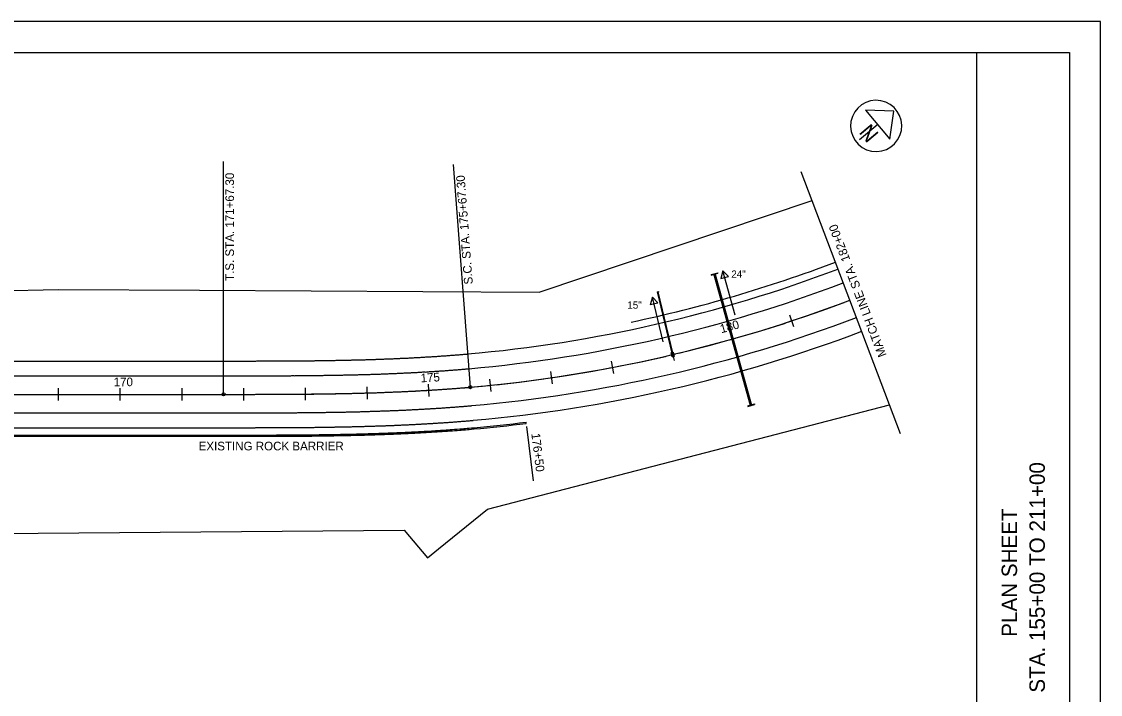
# Model space of a CAD drawing. Extents: x 0 to 3400, y 0 to 2200.
# Drawn here: x 1652 to 3400, y 1110 to 2200 of the extents above; entities that cross this region are included whole.
import ezdxf

# ---------------------------------------------------------------- set-up
doc = ezdxf.new("R2010")
doc.units = 0
for name, color, linetype in [('Default', 7, 'Continuous'), ('DR_X_Culvert', 7, 'Continuous'), ('DR_X_Text', 7, 'Continuous'), ('GE_P_CL_100', 7, 'Continuous'), ('PV_P_EOP', 7, 'Continuous'), ('PV_X_EOP', 7, 'Continuous'), ('RD_X_GR_Lt', 7, 'Continuous'), ('RW_X_Esmt_LA', 7, 'Continuous'), ('SC_Scratch10', 7, 'Continuous'), ('SH_Border', 7, 'Continuous'), ('SH_Cut_Line', 7, 'Continuous'), ('SH_Data', 7, 'Continuous')]:
    doc.layers.add(name, color=color, linetype=linetype)

msp = doc.modelspace()

# ---------------------------------------------------------------- linework, layer by layer
at = {"layer": 'Default'}
for p, q in [((2995.2, 1745.7), (2994.1, 1748.5)), ((2903.1, 1705.5), (2896.7, 1724.4)), ((2648.5, 1702.5), (2648.5, 1702.5)), ((2807, 1676.1), (2801.6, 1695.3)), ((2804.3, 1685.7), (2804.3, 1685.7)), ((2709.9, 1650.8), (2705.2, 1670.2)), ((2707.5, 1660.5), (2707.5, 1660.5)), ((2611.6, 1629.8), (2607.9, 1649.5)), ((2512.6, 1613.1), (2509.7, 1632.9)), ((2212.6, 1588.2), (2212, 1608.2)), ((2312.8, 1592.6), (2311.6, 1612.6)), ((2412.9, 1600.6), (2411, 1620.5)), ((312.1, 1595.9), (1979.7, 1595.9)), ((1712.3, 1585.9), (1712.3, 1605.9)), ((1812.3, 1585.9), (1812.3, 1605.9)), ((1912.3, 1585.9), (1912.3, 1605.9)), ((2012.3, 1585.9), (2012.3, 1605.9)), ((2112.4, 1586.3), (2112.2, 1606.3)), ((2312.2, 1602.6), (2312.2, 1602.6))]:
    msp.add_line(p, q, dxfattribs=at)
for points in [[(2989.5, 1746.7), (2994.1, 1748.5)], [(2909.4, 1718.2), (2925.7, 1723.7), (2963.4, 1737.1), (2984.8, 1745)], [(2895.2, 1713.4), (2899.9, 1715)], [(2899.9, 1715), (2904.7, 1716.6)], [(2813.9, 1688.4), (2849.7, 1698.9), (2888, 1710.9), (2890.4, 1711.8)], [(2717.3, 1662.8), (2734, 1666.9), (2772.9, 1677), (2794.7, 1683)], [(2799.5, 1684.4), (2804.3, 1685.7)], [(2804.3, 1685.7), (2809.1, 1687.1)], [(2702.7, 1659.3), (2707.5, 1660.5)], [(2707.5, 1660.5), (2712.4, 1661.6)], [(2619.6, 1641.5), (2656.2, 1648.8), (2695.3, 1657.5), (2697.8, 1658.1)], [(2521, 1624.5), (2538.3, 1627), (2577.7, 1633.6), (2599.9, 1637.8)], [(2604.8, 1638.7), (2609.7, 1639.6)], [(2609.7, 1639.6), (2614.7, 1640.6)], [(2322.2, 1603.2), (2324.2, 1603.4), (2327.2, 1603.6), (2330.3, 1603.8), (2333.4, 1604), (2336.4, 1604.2), (2339.5, 1604.4), (2342.6, 1604.6), (2345.6, 1604.8), (2348.7, 1605.1), (2351.8, 1605.3), (2354.8, 1605.5), (2357.9, 1605.8), (2361, 1606), (2364.1, 1606.3), (2367.1, 1606.5), (2370.2, 1606.8), (2373.3, 1607), (2376.3, 1607.3), (2379.4, 1607.6), (2379.4, 1607.6), (2402, 1609.7)], [(2406.9, 1610.1), (2411.9, 1610.6)], [(2411.9, 1610.6), (2416.9, 1611.1)], [(2421.9, 1611.6), (2458.9, 1615.9), (2498.5, 1621.2), (2501.2, 1621.6)], [(2506.2, 1622.3), (2511.1, 1623)], [(2511.1, 1623), (2516.1, 1623.8)], [(1622.3, 1595.9), (1702.3, 1595.9)], [(1707.3, 1595.9), (1717.3, 1595.9)], [(1722.3, 1595.9), (1802.3, 1595.9)], [(1807.3, 1595.9), (1817.3, 1595.9)], [(1822.3, 1595.9), (1902.3, 1595.9)], [(1907.3, 1595.9), (1917.3, 1595.9)], [(1922.3, 1595.9), (1979.7, 1595.9), (1979.7, 1595.9), (1982.8, 1595.9), (1985.8, 1595.9), (1988.9, 1595.9), (1992, 1595.9), (1995.1, 1595.9), (1998.1, 1595.9), (2001.2, 1595.9), (2002.3, 1595.9)], [(2007.3, 1595.9), (2007.4, 1595.9), (2010.5, 1595.9), (2013.5, 1595.9), (2016.6, 1595.9), (2017.3, 1595.9)], [(2022.3, 1595.9), (2022.8, 1595.9), (2025.8, 1595.9), (2028.9, 1595.9), (2032, 1596), (2035.1, 1596), (2038.1, 1596), (2041.2, 1596), (2044.3, 1596), (2047.4, 1596), (2050.4, 1596), (2053.5, 1596), (2056.6, 1596), (2059.7, 1596), (2062.8, 1596), (2065.8, 1596), (2068.9, 1596.1), (2072, 1596.1), (2075.1, 1596.1), (2078.1, 1596.1), (2081.2, 1596.1), (2084.3, 1596.1), (2087.4, 1596.2), (2090.4, 1596.2), (2093.5, 1596.2), (2096.6, 1596.2), (2099.7, 1596.2), (2102.3, 1596.3)], [(2107.3, 1596.3), (2108.9, 1596.3), (2112, 1596.3), (2115.1, 1596.4), (2117.3, 1596.4)], [(2122.3, 1596.5), (2124.3, 1596.5), (2127.4, 1596.5), (2130.4, 1596.5), (2133.5, 1596.6), (2136.6, 1596.6), (2139.7, 1596.7), (2142.8, 1596.7), (2145.8, 1596.8), (2148.9, 1596.8), (2152, 1596.9), (2155.1, 1596.9), (2158.1, 1597), (2161.2, 1597), (2164.3, 1597.1), (2167.4, 1597.1), (2170.4, 1597.2), (2173.5, 1597.2), (2176.6, 1597.3), (2179.7, 1597.4), (2182.7, 1597.4), (2185.8, 1597.5), (2188.9, 1597.6), (2192, 1597.7), (2195, 1597.7), (2198.1, 1597.8), (2201.2, 1597.9), (2202.3, 1597.9)], [(2207.3, 1598.1), (2207.4, 1598.1), (2210.4, 1598.2), (2213.5, 1598.2), (2216.6, 1598.3), (2217.3, 1598.4)], [(2222.3, 1598.5), (2222.7, 1598.5), (2225.8, 1598.6), (2228.9, 1598.7), (2232, 1598.8), (2235, 1599), (2238.1, 1599.1), (2241.2, 1599.2), (2244.3, 1599.3), (2247.3, 1599.4), (2250.4, 1599.5), (2253.5, 1599.7), (2256.6, 1599.8), (2259.6, 1599.9), (2262.7, 1600), (2265.8, 1600.2), (2268.8, 1600.3), (2271.9, 1600.5), (2275, 1600.6), (2278.1, 1600.8), (2281.1, 1600.9), (2284.2, 1601.1), (2287.3, 1601.2), (2290.4, 1601.4), (2293.4, 1601.5), (2296.5, 1601.7), (2299.6, 1601.9), (2302.3, 1602)], [(2307.2, 1602.3), (2308.8, 1602.4), (2311.9, 1602.6), (2312.1, 1602.6), (2312.2, 1602.6)], [(2312.2, 1602.6), (2315.1, 1602.8), (2317.2, 1602.9)]]:
    msp.add_lwpolyline(points, dxfattribs=at)
msp.add_arc((2179.6, 3890.7), 2291.8, 274.9999, 290.8177, dxfattribs=at)
for points in [[(1979.7, 1595.9), (1985.8, 1595.9), (1992, 1595.9), (1998.1, 1595.9), (2004.3, 1595.9), (2010.5, 1595.9), (2016.6, 1595.9), (2022.8, 1595.9), (2028.9, 1595.9), (2035.1, 1596), (2041.2, 1596), (2047.4, 1596), (2053.5, 1596), (2059.7, 1596), (2065.8, 1596), (2072, 1596.1), (2078.1, 1596.1), (2084.3, 1596.1), (2090.4, 1596.2), (2096.6, 1596.2), (2102.8, 1596.3), (2108.9, 1596.3), (2115.1, 1596.4), (2121.2, 1596.4), (2127.4, 1596.5), (2133.5, 1596.6), (2139.7, 1596.7), (2145.8, 1596.8), (2152, 1596.9), (2158.1, 1597), (2164.3, 1597.1), (2170.4, 1597.2), (2176.6, 1597.3), (2182.7, 1597.4), (2188.9, 1597.6), (2195, 1597.7), (2201.2, 1597.9), (2207.4, 1598.1), (2213.5, 1598.2), (2219.7, 1598.4), (2225.8, 1598.6), (2232, 1598.8), (2238.1, 1599.1), (2244.3, 1599.3), (2250.4, 1599.5), (2256.6, 1599.8), (2262.7, 1600), (2268.8, 1600.3), (2275, 1600.6), (2281.1, 1600.9), (2287.3, 1601.2), (2293.4, 1601.5), (2299.6, 1601.9), (2305.7, 1602.2), (2311.9, 1602.6), (2312.2, 1602.6)], [(2312.2, 1602.6), (2318, 1603), (2324.2, 1603.4), (2330.3, 1603.8), (2336.4, 1604.2), (2342.6, 1604.6), (2348.7, 1605.1), (2354.8, 1605.5), (2361, 1606), (2367.1, 1606.5), (2373.3, 1607), (2379.4, 1607.6)]]:
    msp.add_spline(points, degree=3, dxfattribs=at)
at = {"layer": 'DR_X_Culvert'}
for p, q in [((2769.4, 1790.2), (2780, 1793.1)), ((2769.4, 1790.2), (2769.7, 1789.2)), ((2769.7, 1789.2), (2780.3, 1792.2)), ((2833.4, 1577.6), (2773.7, 1791.4)), ((2835.4, 1578.1), (2775.7, 1791.9)), ((2780, 1793.1), (2780.3, 1792.2)), ((2681.9, 1762), (2683.9, 1762.4)), ((2681.9, 1762), (2682.1, 1761)), ((2682.1, 1761), (2684.2, 1761.5)), ((2706.3, 1662.9), (2682.3, 1762.1)), ((2707.5, 1663.2), (2683.5, 1762.3)), ((2683.9, 1762.4), (2684.2, 1761.5)), ((2704.8, 1663.2), (2708.7, 1664.2)), ((2706.4, 1656.8), (2704.8, 1663.2)), ((2705.6, 1662.7), (2708.2, 1663.4)), ((2706.9, 1657.6), (2705.6, 1662.7)), ((2709.4, 1658.2), (2708.2, 1663.4)), ((2710.3, 1657.7), (2708.7, 1664.2)), ((2706.4, 1656.8), (2710.3, 1657.7)), ((2706.9, 1657.6), (2709.4, 1658.2)), ((2828.8, 1577.3), (2839.4, 1580.3)), ((2828.8, 1577.3), (2829.1, 1576.4)), ((2829.1, 1576.4), (2839.7, 1579.3)), ((2839.4, 1580.3), (2839.7, 1579.3))]:
    msp.add_line(p, q, dxfattribs=at)
at = {"layer": 'DR_X_Text'}
for p, q in [((2788.4, 1796), (2785.2, 1783.7)), ((2785.2, 1783.8), (2797.4, 1787.1)), ((2797.4, 1787.1), (2788.4, 1796)), ((2808.3, 1724.4), (2788.4, 1796)), ((2674.4, 1753.4), (2670.8, 1741.2)), ((2683.2, 1744.2), (2674.4, 1753.4)), ((2691.9, 1681.2), (2674.4, 1753.4)), ((2670.9, 1741.4), (2683.2, 1744.2))]:
    msp.add_line(p, q, dxfattribs=at)
at = {"layer": 'PV_P_EOP'}
for p, q in [((312.1, 1649.9), (1979.7, 1649.9)), ((312.1, 1625.9), (1979.7, 1625.9)), ((312.1, 1565.9), (1979.7, 1565.9)), ((312.1, 1541.9), (1979.7, 1541.9))]:
    msp.add_line(p, q, dxfattribs=at)
for radius in [2237.8, 2261.8, 2321.8, 2345.8]:
    msp.add_arc((2179.6, 3890.7), radius, 274.9999, 290.8177, dxfattribs=at)
for points in [[(2309, 1656.5), (2314.6, 1656.9), (2320.7, 1657.2), (2326.7, 1657.6), (2332.7, 1658.1), (2338.7, 1658.5), (2344.7, 1658.9), (2350.7, 1659.4), (2356.7, 1659.8), (2362.7, 1660.3), (2368.7, 1660.8), (2374.7, 1661.3)], [(1979.7, 1649.9), (1985.8, 1649.9), (1992, 1649.9), (1998.1, 1649.9), (2004.3, 1649.9), (2010.4, 1649.9), (2016.6, 1649.9), (2022.7, 1649.9), (2028.8, 1649.9), (2035, 1650), (2041.1, 1650), (2047.2, 1650), (2053.4, 1650), (2059.5, 1650), (2065.6, 1650), (2071.7, 1650.1), (2077.9, 1650.1), (2084, 1650.1), (2090.1, 1650.2), (2096.2, 1650.2), (2102.3, 1650.3), (2108.4, 1650.3), (2114.5, 1650.4), (2120.6, 1650.4), (2126.7, 1650.5), (2132.8, 1650.6), (2138.9, 1650.7), (2145, 1650.8), (2151.1, 1650.8), (2157.2, 1650.9), (2163.3, 1651.1), (2169.4, 1651.2), (2175.5, 1651.3), (2181.5, 1651.4), (2187.6, 1651.6), (2193.7, 1651.7), (2199.8, 1651.9), (2205.8, 1652), (2211.9, 1652.2), (2218, 1652.4), (2224, 1652.6), (2230.1, 1652.8), (2236.1, 1653), (2242.2, 1653.3), (2248.2, 1653.5), (2254.3, 1653.7), (2260.3, 1654), (2266.4, 1654.3), (2272.4, 1654.5), (2278.5, 1654.8), (2284.5, 1655.1), (2290.5, 1655.5), (2296.6, 1655.8), (2302.6, 1656.1), (2308.6, 1656.5), (2309, 1656.5)], [(1979.7, 1625.9), (1985.8, 1625.9), (1992, 1625.9), (1998.1, 1625.9), (2004.3, 1625.9), (2010.4, 1625.9), (2016.6, 1625.9), (2022.7, 1625.9), (2028.9, 1625.9), (2035, 1626), (2041.2, 1626), (2047.3, 1626), (2053.4, 1626), (2059.6, 1626), (2065.7, 1626), (2071.8, 1626.1), (2078, 1626.1), (2084.1, 1626.1), (2090.2, 1626.2), (2096.4, 1626.2), (2102.5, 1626.3), (2108.6, 1626.3), (2114.8, 1626.4), (2120.9, 1626.4), (2127, 1626.5), (2133.1, 1626.6), (2139.3, 1626.7), (2145.4, 1626.8), (2151.5, 1626.8), (2157.6, 1627), (2163.7, 1627.1), (2169.8, 1627.2), (2176, 1627.3), (2182.1, 1627.4), (2188.2, 1627.6), (2194.3, 1627.7), (2200.4, 1627.9), (2206.5, 1628.1), (2212.6, 1628.2), (2218.7, 1628.4), (2224.8, 1628.6), (2230.9, 1628.8), (2237, 1629), (2243.1, 1629.3), (2249.2, 1629.5), (2255.3, 1629.8), (2261.4, 1630), (2267.5, 1630.3), (2273.6, 1630.6), (2279.7, 1630.9), (2285.7, 1631.2), (2291.8, 1631.5), (2297.9, 1631.8), (2304, 1632.2), (2310.1, 1632.5), (2310.4, 1632.6)], [(2310.4, 1632.6), (2316.1, 1632.9), (2322.2, 1633.3), (2328.3, 1633.7), (2334.4, 1634.1), (2340.4, 1634.5), (2346.5, 1635), (2352.5, 1635.4), (2358.6, 1635.9), (2364.7, 1636.4), (2370.7, 1636.9), (2376.8, 1637.4)], [(2314.1, 1572.7), (2319.9, 1573), (2326.1, 1573.4), (2332.3, 1573.8), (2338.5, 1574.3), (2344.7, 1574.7), (2350.9, 1575.2), (2357.2, 1575.6), (2363.4, 1576.1), (2369.6, 1576.6), (2375.8, 1577.1), (2382, 1577.7)], [(1979.7, 1565.9), (1985.8, 1565.9), (1992, 1565.9), (1998.1, 1565.9), (2004.3, 1565.9), (2010.5, 1565.9), (2016.6, 1565.9), (2022.8, 1565.9), (2029, 1565.9), (2035.1, 1566), (2041.3, 1566), (2047.4, 1566), (2053.6, 1566), (2059.8, 1566), (2066, 1566), (2072.1, 1566.1), (2078.3, 1566.1), (2084.5, 1566.1), (2090.6, 1566.2), (2096.8, 1566.2), (2103, 1566.3), (2109.2, 1566.3), (2115.4, 1566.4), (2121.5, 1566.4), (2127.7, 1566.5), (2133.9, 1566.6), (2140.1, 1566.7), (2146.3, 1566.8), (2152.5, 1566.9), (2158.7, 1567), (2164.8, 1567.1), (2171, 1567.2), (2177.2, 1567.3), (2183.4, 1567.5), (2189.6, 1567.6), (2195.8, 1567.7), (2202, 1567.9), (2208.2, 1568.1), (2214.4, 1568.3), (2220.6, 1568.5), (2226.8, 1568.7), (2233, 1568.9), (2239.2, 1569.1), (2245.4, 1569.3), (2251.6, 1569.6), (2257.8, 1569.8), (2264, 1570.1), (2270.2, 1570.4), (2276.4, 1570.6), (2282.6, 1570.9), (2288.8, 1571.3), (2295, 1571.6), (2301.3, 1571.9), (2307.5, 1572.3), (2313.7, 1572.6), (2314.1, 1572.7)], [(1979.7, 1541.9), (1985.8, 1541.9), (1992, 1541.9), (1998.2, 1541.9), (2004.3, 1541.9), (2010.5, 1541.9), (2016.6, 1541.9), (2022.8, 1541.9), (2029, 1541.9), (2035.2, 1542), (2041.3, 1542), (2047.5, 1542), (2053.7, 1542), (2059.9, 1542), (2066, 1542), (2072.2, 1542.1), (2078.4, 1542.1), (2084.6, 1542.1), (2090.8, 1542.2), (2097, 1542.2), (2103.2, 1542.3), (2109.4, 1542.3), (2115.6, 1542.4), (2121.8, 1542.4), (2128, 1542.5), (2134.2, 1542.6), (2140.4, 1542.7), (2146.6, 1542.8), (2152.9, 1542.9), (2159.1, 1543), (2165.3, 1543.1), (2171.5, 1543.2), (2177.7, 1543.3), (2184, 1543.5), (2190.2, 1543.6), (2196.4, 1543.8), (2202.6, 1543.9), (2208.9, 1544.1), (2215.1, 1544.3), (2221.4, 1544.5), (2227.6, 1544.7), (2233.8, 1544.9), (2240.1, 1545.1), (2246.3, 1545.3), (2252.6, 1545.6), (2258.8, 1545.8), (2265.1, 1546.1), (2271.3, 1546.4), (2277.6, 1546.7), (2283.8, 1547), (2290.1, 1547.3), (2296.3, 1547.6), (2302.6, 1548), (2308.9, 1548.3), (2315.1, 1548.7), (2315.5, 1548.7)], [(2315.5, 1548.7), (2321.4, 1549.1), (2327.7, 1549.5), (2333.9, 1549.9), (2340.2, 1550.3), (2346.5, 1550.8), (2352.7, 1551.2), (2359, 1551.7), (2365.3, 1552.2), (2371.5, 1552.7), (2377.8, 1553.2), (2384.1, 1553.8)]]:
    msp.add_spline(points, degree=3, dxfattribs=at)
at = {"layer": 'PV_X_EOP'}
for p, q in [((2470, 1548.8), (2469.7, 1550.7)), ((1612.3, 1529.9), (1979.7, 1529.9)), ((1612.3, 1527.9), (1979.7, 1527.9))]:
    msp.add_line(p, q, dxfattribs=at)
for radius in [2357.8, 2359.8]:
    msp.add_arc((2179.6, 3890.7), radius, 274.9999, 277.0669, dxfattribs=at)
for points in [[(2316.3, 1536.7), (2322, 1537.1), (2327.7, 1537.4), (2339.2, 1538.2), (2345, 1538.6), (2362.2, 1539.9), (2373.7, 1540.8), (2385.1, 1541.8)], [(2316.4, 1534.7), (2322.1, 1535.1), (2327.9, 1535.5), (2339.4, 1536.2), (2345.1, 1536.6), (2362.3, 1537.9), (2373.8, 1538.8), (2385.3, 1539.8)], [(1979.7, 1529.9), (1986.7, 1529.9), (1993.7, 1529.9), (2007.7, 1529.9), (2014.7, 1529.9), (2028.7, 1529.9), (2035.7, 1530), (2049.7, 1530), (2060.2, 1530), (2070.7, 1530.1), (2077.7, 1530.1), (2081.2, 1530.1), (2088.2, 1530.2), (2091.8, 1530.2), (2098.8, 1530.2), (2102.3, 1530.3), (2112.8, 1530.3), (2119.8, 1530.4), (2130.3, 1530.5), (2133.8, 1530.6), (2140.8, 1530.7), (2144.3, 1530.7), (2154.8, 1530.9), (2161.9, 1531), (2175.9, 1531.3), (2182.9, 1531.4), (2193.4, 1531.7), (2196.9, 1531.8), (2204, 1531.9), (2211, 1532.1), (2218, 1532.4), (2225, 1532.6), (2228.5, 1532.7), (2233.8, 1532.9), (2235.5, 1532.9), (2239.1, 1533.1), (2240.8, 1533.1), (2246.1, 1533.3), (2253.1, 1533.6), (2260.1, 1533.9), (2267.1, 1534.2), (2270.6, 1534.3), (2281.2, 1534.8), (2288.2, 1535.2), (2302.2, 1535.9), (2309.2, 1536.3), (2316.2, 1536.7)], [(1979.7, 1527.9), (1986.7, 1527.9), (1993.7, 1527.9), (2007.7, 1527.9), (2014.7, 1527.9), (2028.7, 1527.9), (2035.7, 1528), (2049.7, 1528), (2056.7, 1528), (2067.2, 1528), (2070.7, 1528.1), (2077.7, 1528.1), (2081.2, 1528.1), (2088.3, 1528.2), (2091.8, 1528.2), (2098.8, 1528.2), (2102.3, 1528.3), (2112.8, 1528.3), (2119.8, 1528.4), (2130.3, 1528.5), (2133.8, 1528.6), (2140.9, 1528.7), (2144.4, 1528.7), (2154.9, 1528.9), (2161.9, 1529), (2175.9, 1529.3), (2183, 1529.4), (2193.5, 1529.7), (2197, 1529.8), (2204, 1529.9), (2207.5, 1530), (2214.5, 1530.2), (2218.1, 1530.4), (2225.1, 1530.6), (2228.6, 1530.7), (2233.9, 1530.9), (2235.6, 1530.9), (2239.1, 1531.1), (2240.9, 1531.1), (2246.1, 1531.3), (2249.6, 1531.5), (2256.7, 1531.7), (2260.2, 1531.9), (2267.2, 1532.2), (2270.7, 1532.3), (2281.3, 1532.8), (2288.3, 1533.2), (2302.3, 1533.9), (2309.3, 1534.3), (2316.4, 1534.7)]]:
    msp.add_open_spline(points, degree=3, dxfattribs=at)
at = {"layer": 'RD_X_GR_Lt'}
msp.add_arc((2179.6, 3890.7), 2225.8, 281.9285, 290.8177, dxfattribs=at)
at = {"layer": 'RW_X_Esmt_LA'}
for p, q in [((2490.9, 1761.5), (2932.8, 1909.9)), ((812.4, 1745.9), (1712.4, 1765.9)), ((1712.4, 1765.9), (1940.4, 1764.6)), ((1940.4, 1764.6), (2302.5, 1762.5)), ((2302.5, 1762.5), (2490.9, 1761.5)), ((2406.9, 1409.9), (3058.6, 1578.9)), ((2327.9, 1345.7), (2406.9, 1409.9)), ((1012.3, 1365.9), (2271.9, 1375.7)), ((2271.9, 1375.7), (2309.9, 1331.1)), ((2309.9, 1331.1), (2327.8, 1345.6))]:
    msp.add_line(p, q, dxfattribs=at)
at = {"layer": 'SC_Scratch10'}
for p, q in [((2639.7, 1712.9), (2639.7, 1712.9)), ((2899.9, 1715), (2899.9, 1715)), ((2804.3, 1685.7), (2804.3, 1685.7)), ((2707.5, 1660.5), (2707.5, 1660.5)), ((2609.7, 1639.6), (2609.7, 1639.6)), ((2411.9, 1610.6), (2411.9, 1610.6)), ((2511.1, 1623), (2511.1, 1623)), ((1712.3, 1595.9), (1712.3, 1595.9)), ((1812.3, 1595.9), (1812.3, 1595.9)), ((1912.3, 1595.9), (1912.3, 1595.9)), ((2012.3, 1595.9), (2012.3, 1595.9)), ((2112.3, 1596.3), (2112.3, 1596.3)), ((2212.3, 1598.2), (2212.3, 1598.2)), ((2312.2, 1602.6), (2312.2, 1602.6))]:
    msp.add_line(p, q, dxfattribs=at)
at = {"layer": 'SH_Border'}
msp.add_line((3200, 50), (3200, 2150), dxfattribs=at)
msp.add_lwpolyline([(150, 2150), (3350, 2150), (3350, 50), (150, 50)], close=True, dxfattribs=at)
at = {"layer": 'SH_Cut_Line'}
msp.add_line((2994.1, 1748.5), (2994.1, 1748.5), dxfattribs=at)
msp.add_lwpolyline([(0, 0), (3400, 0), (3400, 2200), (0, 2200)], close=True, dxfattribs=at)
at = {"layer": 'SH_Data'}
for p, q in [((3065.3, 2054.9), (3019.4, 2056.5)), ((3019.4, 2056.5), (3058.9, 2009.4)), ((3058.9, 2009.4), (3065.3, 2054.9)), ((3039.2, 2033), (3009.5, 2008.1)), ((3036.7, 2030.9), (3036.7, 2030.9)), ((3036.7, 2030.9), (3036.7, 2030.9)), ((1979.7, 1595.9), (1979.7, 1973.2)), ((2379.4, 1607.6), (2352.3, 1968.5)), ((3076.4, 1532.1), (2915, 1956.6)), ((2481.5, 1455.6), (2470.6, 1543.8))]:
    msp.add_line(p, q, dxfattribs=at)
for centre in [(2379.4, 1607.6), (1979.7, 1595.9)]:
    msp.add_circle(centre, 2.5, dxfattribs=at)
msp.add_arc((3036.7, 2030.9), 41.5, 79.7337, 79.7172, dxfattribs=at)

# ---------------------------------------------------------------- texts
at = {"layer": 'DR_X_Text'}
for s, p in [('24"', (2802.1, 1784.8)), ('15"', (2633.7, 1734.7))]:
    msp.add_text(s, height=11.86, dxfattribs=at).set_placement(p)
at = {"layer": 'GE_P_CL_100'}
for s, rotation, p in [('T.S. STA. 171+67.30', 89.9998, (1996.5, 1779.7)), ('S.C. STA. 175+67.30', 94.2901, (2383.4, 1774.5)), ('180', 15.5975, (2786, 1694.8)), ('175', 3.3877, (2299.2, 1615.3)), ('170', 359.9974, (1801.6, 1609.1))]:
    msp.add_text(s, height=14, rotation=rotation, dxfattribs=at).set_placement(p)
at = {"layer": 'SH_Data'}
for s, height, rotation, p in [('N', 25, 309.9539, (3007.7, 2020.2)), ('MATCH LINE STA. 182+00', 14, 110.8177, (3053.8, 1659.5)), ('176+50', 14, 277.0669, (2478.1, 1532.2)), ('EXISTING ROCK BARRIER', 14, 0.0166, (1939.2, 1505.1)), ('STA. 155+00 TO 211+00', 25, 90, (3310, 1112.5)), ('PLAN SHEET', 25, 90, (3265, 1203))]:
    msp.add_text(s, height=height, rotation=rotation, dxfattribs=at).set_placement(p)

doc.saveas('drawing.dxf')
